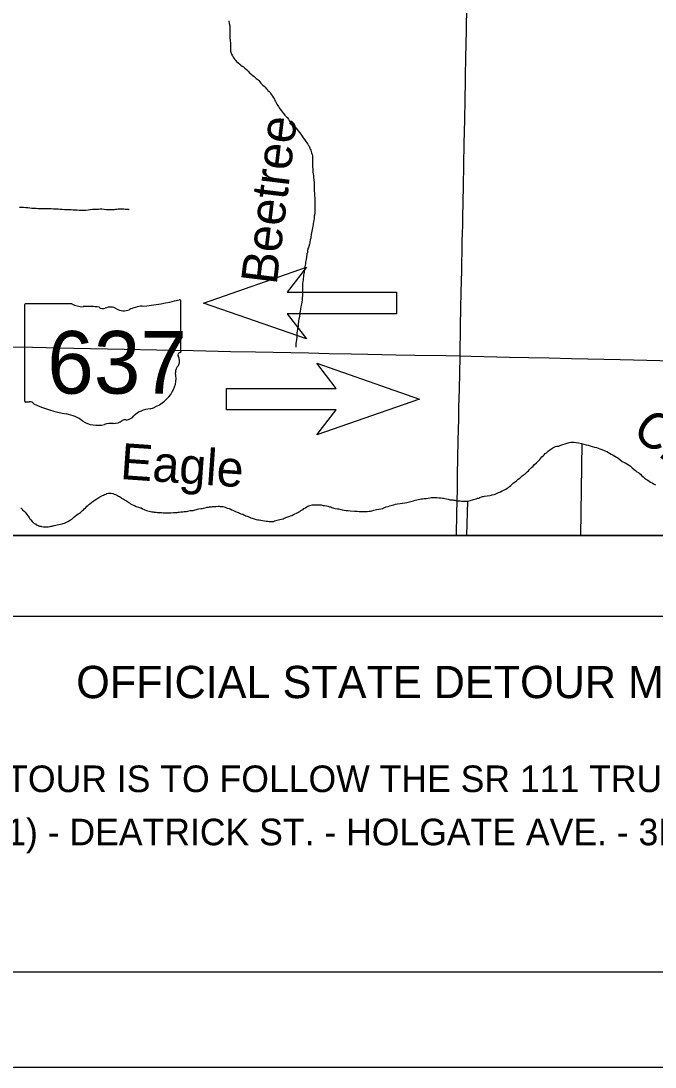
# Model space of a CAD drawing. Extents: x -483 to 680, y 0 to 440.
# Drawn here: x 177 to 243.8, y 0 to 110.1 of the extents above; entities that cross this region are included whole.
import ezdxf

# ---------------------------------------------------------------- set-up
doc = ezdxf.new("R2010")
doc.units = 0
for name, color, linetype in [('Default', 7, 'Continuous'), ('GM_X_Minor_Lake_Text', 7, 'Continuous'), ('GM_X_Minor_River', 7, 'Continuous'), ('GM_X_State_Location', 7, 'Continuous'), ('GM_X_State_Route', 7, 'Continuous'), ('GM_X_State_Shield', 7, 'Continuous'), ('GM_X_Township_Road', 7, 'Continuous'), ('PM_P_Cells', 7, 'Continuous'), ('SH_Border', 7, 'Continuous'), ('SH_Cut_Line', 7, 'Continuous'), ('SH_Text', 7, 'Continuous')]:
    doc.layers.add(name, color=color, linetype=linetype)

msp = doc.modelspace()

# ---------------------------------------------------------------- linework, layer by layer
at = {"layer": 'GM_X_Minor_River'}
for p, q in [((236.06, 65.64), (235.9, 55.95)), ((224.01, 59.59), (223.91, 55.95))]:
    msp.add_line(p, q, dxfattribs=at)
for points in [[(198.88, 110.16), (198.92, 109.88), (198.98, 109.61), (198.99, 109.37), (199.01, 109.14), (199.01, 108.93)], [(199.01, 108.93), (198.99, 108.74), (198.99, 108.57), (198.99, 108.43), (199.01, 108.3), (199.03, 108.19), (199.03, 108.02), (199.05, 107.86), (199.05, 107.64), (199.05, 107.48), (199.05, 107.39), (199.05, 107.28), (199.07, 107.14), (199.08, 106.95), (199.1, 106.84), (199.18, 106.63), (199.27, 106.48), (199.33, 106.34), (199.43, 106.21), (199.52, 106.06), (199.62, 105.96), (199.71, 105.87), (200.03, 105.58), (200.17, 105.49), (200.3, 105.39), (200.43, 105.29), (200.58, 105.16), (200.75, 105.01), (200.93, 104.86), (201.08, 104.68), (201.25, 104.53), (201.4, 104.4), (201.55, 104.28), (201.78, 104.09), (201.93, 103.96), (202.04, 103.85), (202.16, 103.71), (202.27, 103.6), (202.37, 103.48), (202.48, 103.37), (202.6, 103.27), (202.71, 103.16), (202.82, 103.04), (202.92, 102.95), (203.01, 102.82), (203.15, 102.7), (203.24, 102.59), (203.32, 102.47), (203.39, 102.36), (203.49, 102.21), (203.58, 102.05), (203.68, 101.9), (203.75, 101.77), (203.81, 101.65), (203.87, 101.52), (203.94, 101.39), (204.04, 101.24), (204.11, 101.12), (204.19, 100.99), (204.3, 100.84), (204.42, 100.68), (204.53, 100.53), (204.66, 100.38), (204.78, 100.23), (204.91, 100.09), (205.02, 99.96), (205.16, 99.81), (205.29, 99.6), (205.48, 99.41), (205.65, 99.22), (205.8, 99.04), (205.95, 98.87), (206.33, 98.4), (206.46, 98.23), (206.6, 98.02), (206.73, 97.83), (206.86, 97.65), (207, 97.43), (207.11, 97.29), (207.2, 97.16), (207.28, 97.04), (207.34, 96.95), (207.37, 96.85), (207.43, 96.74), (207.47, 96.64), (207.51, 96.53), (207.56, 96.4), (207.6, 96.26), (207.64, 96.15), (207.68, 96.06), (207.7, 95.94), (207.7, 95.85), (207.71, 95.69), (207.71, 95.6), (207.71, 95.43), (207.71, 95.33), (207.71, 95.24), (207.71, 95.12), (207.71, 94.93), (207.71, 94.76), (207.73, 94.53)], [(207.73, 94.53), (207.73, 94.36), (207.75, 94.21), (207.77, 94.04), (207.79, 93.83), (207.81, 93.72), (207.82, 93.6), (207.84, 93.45), (207.84, 93.34), (207.86, 93.18), (207.86, 93.07), (207.86, 92.98), (207.86, 92.84), (207.88, 92.69), (207.88, 92.58), (207.88, 92.48), (207.88, 92.33), (207.88, 92.22), (207.9, 91.99), (207.92, 91.68), (207.93, 91.55), (207.93, 91.42), (207.93, 91.21), (207.93, 91.07), (207.93, 90.98), (207.93, 90.81), (207.93, 90.66), (207.93, 90.52), (207.93, 90.37), (207.93, 90.24), (207.93, 90.12), (207.93, 89.93), (207.91, 89.69), (207.89, 89.59), (207.89, 89.5), (207.87, 89.33), (207.85, 89.12), (207.82, 88.98), (207.78, 88.79), (207.74, 88.51), (207.7, 88.36), (207.66, 88.19), (207.64, 88.02), (207.6, 87.84), (207.57, 87.64), (207.53, 87.39), (207.51, 87.27), (207.47, 87.1), (207.43, 86.89), (207.41, 86.78), (207.37, 86.63), (207.32, 86.38), (207.26, 86.27), (207.22, 86.17), (207.2, 86.08), (207.18, 85.98), (207.16, 85.74), (207.11, 85.64), (207.09, 85.51), (207.07, 85.34), (207.05, 85.24), (207.03, 85.05), (206.99, 84.86), (206.97, 84.77), (206.95, 84.56), (206.91, 84.44), (206.87, 84.12), (206.84, 83.97), (206.82, 83.7), (206.78, 83.51), (206.76, 83.38), (206.74, 83.21), (206.72, 83.04), (206.7, 82.89), (206.68, 82.66), (206.66, 82.53), (206.64, 82.32), (206.64, 82.09), (206.64, 81.82), (206.64, 81.69), (206.64, 81.52), (206.64, 81.2), (206.62, 81.02), (206.6, 80.82), (206.56, 80.49), (206.51, 80.21), (206.47, 80), (206.45, 79.85), (206.43, 79.75), (206.41, 79.6), (206.37, 79.37), (206.33, 79.05), (206.27, 78.74), (206.24, 78.57), (206.22, 78.38), (206.2, 78.27), (206.18, 77.98), (206.12, 77.72), (206.08, 77.41), (206.04, 77.3), (206.04, 76.86)], [(176.86, 90.54), (177.07, 90.52), (177.28, 90.52), (177.51, 90.5), (177.72, 90.48), (177.93, 90.46), (178.14, 90.42), (178.4, 90.42), (178.61, 90.42), (178.8, 90.4), (179.01, 90.4), (179.2, 90.4), (179.39, 90.4), (179.58, 90.4), (180.19, 90.38), (180.42, 90.36), (180.7, 90.34), (180.91, 90.34), (181.12, 90.32), (181.35, 90.32), (181.58, 90.3), (181.83, 90.3), (182.05, 90.28), (182.28, 90.28), (182.51, 90.26), (182.72, 90.26), (182.93, 90.24), (183.12, 90.23), (183.38, 90.23), (183.61, 90.23), (183.84, 90.23), (184.07, 90.25), (184.3, 90.27), (184.54, 90.31), (184.79, 90.31), (185, 90.32), (185.17, 90.32), (185.34, 90.34), (185.51, 90.34), (185.78, 90.32), (185.99, 90.3), (186.16, 90.3), (186.31, 90.28), (186.45, 90.28), (186.58, 90.28), (186.67, 90.28), (186.81, 90.3), (186.96, 90.32), (187.09, 90.32), (187.24, 90.34), (187.38, 90.34), (187.53, 90.34), (187.64, 90.34), (187.74, 90.34), (187.83, 90.34), (187.99, 90.32), (188.16, 90.32), (188.27, 90.31), (188.33, 90.3), (188.35, 90.31), (188.39, 90.28)], [(206.04, 76.86), (205.97, 76.37), (205.96, 76.18), (205.95, 75.91), (205.93, 75.78), (205.93, 75.78)], [(223.25, 59.6), (223.39, 59.59), (223.54, 59.59), (223.67, 59.59), (223.82, 59.59), (223.99, 59.59), (224.17, 59.61), (224.32, 59.65), (224.41, 59.69), (224.53, 59.72), (224.66, 59.76), (224.79, 59.8), (224.93, 59.84), (225.08, 59.89), (225.21, 59.91), (225.31, 59.95), (225.5, 60.03), (225.59, 60.06), (225.69, 60.08), (225.8, 60.12), (226.37, 60.18), (226.52, 60.21), (226.62, 60.23), (226.81, 60.29), (226.94, 60.33), (227.06, 60.38), (227.27, 60.48), (227.48, 60.55), (227.67, 60.65), (227.86, 60.72), (228.05, 60.84), (228.2, 60.93), (228.33, 61.01), (228.45, 61.12), (228.58, 61.23), (228.71, 61.37), (228.87, 61.5), (229.02, 61.63), (229.21, 61.76), (229.36, 61.88), (229.53, 61.99), (229.65, 62.1), (229.78, 62.24), (229.97, 62.39), (230.16, 62.54), (230.31, 62.65), (230.43, 62.77), (230.52, 62.86), (230.62, 62.98), (230.77, 63.13), (230.92, 63.28), (231.09, 63.45), (231.27, 63.6), (231.4, 63.73), (231.53, 63.87), (231.63, 63.98), (231.74, 64.11), (231.86, 64.23), (231.97, 64.36), (232.1, 64.45), (232.2, 64.59), (232.33, 64.68), (232.43, 64.78), (232.52, 64.85), (232.7, 65), (232.79, 65.06), (232.89, 65.14), (233, 65.21), (233.3, 65.32), (233.42, 65.36), (233.53, 65.36), (233.63, 65.38), (233.84, 65.46), (234.07, 65.53), (234.31, 65.63), (234.52, 65.68), (234.71, 65.74), (234.9, 65.78), (235.07, 65.79), (235.26, 65.79), (235.47, 65.77), (235.7, 65.72), (236.02, 65.66), (236.25, 65.58), (236.5, 65.52), (236.73, 65.47), (236.94, 65.41), (237.16, 65.35), (237.39, 65.27), (237.6, 65.22), (237.77, 65.16), (237.96, 65.1), (238.17, 65.03), (238.42, 64.91), (238.57, 64.85), (238.7, 64.8), (239.14, 64.53), (239.35, 64.43), (239.52, 64.32), (239.69, 64.22), (239.86, 64.13)], [(239.86, 64.13), (240.05, 63.97), (240.32, 63.76), (240.62, 63.63), (240.81, 63.52), (240.98, 63.4), (241.13, 63.31), (241.25, 63.19), (241.36, 63.08), (241.55, 62.91), (241.7, 62.81), (241.84, 62.68), (242.01, 62.58), (242.1, 62.52), (242.22, 62.41), (242.39, 62.26), (242.5, 62.14), (242.67, 61.99), (242.86, 61.86), (242.99, 61.78), (243.13, 61.69), (243.3, 61.59), (243.47, 61.51), (243.6, 61.42), (243.81, 61.3)], [(176.99, 58.88), (177.08, 58.8), (177.16, 58.68), (177.33, 58.51), (177.43, 58.42), (177.54, 58.28), (177.63, 58.17), (177.73, 58.02), (177.86, 57.87), (177.94, 57.73), (178.05, 57.6), (178.18, 57.45), (178.28, 57.35), (178.41, 57.24), (178.53, 57.18), (178.62, 57.1), (178.73, 57.05), (178.87, 56.99), (178.96, 56.95), (179.08, 56.93), (179.17, 56.91), (179.36, 56.89), (179.7, 56.87), (179.88, 56.87), (180.07, 56.91), (180.18, 56.93), (180.29, 56.96), (180.39, 56.98), (180.5, 57.02), (180.66, 57.06), (180.81, 57.08), (180.98, 57.11), (181.17, 57.15), (181.34, 57.19), (181.45, 57.21), (181.57, 57.27), (181.74, 57.34), (181.85, 57.4), (181.95, 57.45), (182.12, 57.55), (182.22, 57.61), (182.35, 57.7), (182.54, 57.85), (182.71, 58), (182.9, 58.15), (183.03, 58.25), (183.17, 58.32), (183.26, 58.4), (183.36, 58.5), (183.47, 58.59), (183.57, 58.67), (183.64, 58.78), (183.78, 58.87), (183.87, 58.95), (183.95, 59.04), (184.04, 59.14), (184.14, 59.22), (184.27, 59.31), (184.39, 59.39), (184.48, 59.46), (184.58, 59.54), (184.69, 59.63), (184.81, 59.73), (185, 59.84), (185.32, 60.05), (185.45, 60.1), (185.59, 60.16), (185.68, 60.2), (185.81, 60.27), (185.93, 60.33), (186.06, 60.37), (186.21, 60.41), (186.39, 60.42), (186.5, 60.41), (186.67, 60.37), (186.8, 60.33), (186.97, 60.27), (187.15, 60.18), (187.28, 60.12), (187.39, 60.06), (187.49, 60), (187.58, 59.91), (187.75, 59.81), (187.87, 59.74), (187.98, 59.68), (188.1, 59.6), (188.21, 59.53), (188.32, 59.45), (188.42, 59.39), (188.53, 59.3), (188.68, 59.22)], [(204.98, 57.9), (205.2, 57.98), (205.38, 58.03), (205.51, 58.07), (205.7, 58.18), (205.83, 58.26), (206, 58.32), (206.16, 58.39), (206.25, 58.45), (206.37, 58.5), (206.48, 58.6), (206.61, 58.66), (206.71, 58.71), (206.8, 58.79), (206.96, 58.86), (207.11, 58.98), (207.22, 59.05), (207.32, 59.09), (207.43, 59.13), (207.66, 59.18), (207.76, 59.18), (207.93, 59.2), (208.12, 59.2), (208.23, 59.2), (208.42, 59.2), (208.61, 59.18), (208.82, 59.14), (208.95, 59.12), (209.18, 59.07), (209.33, 59.05), (209.48, 58.99), (209.64, 58.99), (209.73, 58.91), (210.06, 58.82), (210.32, 58.76), (210.42, 58.76), (210.82, 58.66), (211.23, 58.6), (211.44, 58.6), (211.65, 58.56), (212.11, 58.53), (212.41, 58.51), (212.62, 58.5), (212.77, 58.49), (212.94, 58.48), (213.17, 58.5), (213.44, 58.5), (213.67, 58.52), (213.82, 58.54), (213.95, 58.56), (214.05, 58.58), (214.16, 58.63), (214.45, 58.69), (214.69, 58.75), (214.9, 58.78), (215.06, 58.82), (215.15, 58.84), (215.27, 58.9), (215.44, 58.97), (215.65, 59.03), (215.85, 59.1), (216.08, 59.16), (216.25, 59.2), (216.43, 59.25), (216.65, 59.31), (216.94, 59.35), (217.19, 59.37), (217.41, 59.4), (217.62, 59.44), (217.78, 59.46), (217.91, 59.5), (218.35, 59.63), (218.5, 59.68), (218.67, 59.72), (218.84, 59.76), (219.01, 59.8), (219.15, 59.82), (219.28, 59.83), (219.45, 59.85), (219.66, 59.87), (219.87, 59.91), (220.04, 59.93), (220.19, 59.95), (220.34, 59.96), (220.57, 59.96), (220.78, 59.96), (221.01, 59.94), (221.22, 59.92), (221.39, 59.9), (221.5, 59.89), (221.64, 59.85), (221.81, 59.83), (221.98, 59.79), (222.19, 59.73), (222.38, 59.71), (222.47, 59.71), (222.59, 59.69), (222.68, 59.67), (222.87, 59.63), (223.08, 59.61), (223.25, 59.6)], [(188.68, 59.22), (188.84, 59.16), (188.95, 59.11), (189.14, 59.03), (189.39, 58.93), (189.56, 58.88), (189.65, 58.86), (189.79, 58.78), (189.98, 58.7), (190.22, 58.61), (190.77, 58.47), (190.91, 58.45), (191.02, 58.43), (191.25, 58.42), (191.38, 58.4), (191.53, 58.4), (191.67, 58.38), (191.8, 58.38), (191.97, 58.36), (192.16, 58.36), (192.29, 58.35), (192.41, 58.34), (192.56, 58.35), (192.77, 58.35), (193.06, 58.37), (193.26, 58.37), (193.44, 58.39), (193.55, 58.41), (193.66, 58.43), (193.84, 58.45), (194.03, 58.46), (194.18, 58.48), (194.29, 58.48), (194.42, 58.5), (194.58, 58.54), (194.81, 58.58), (194.98, 58.59), (195.13, 58.61), (195.24, 58.63), (195.34, 58.65), (195.47, 58.69), (195.6, 58.73), (195.74, 58.76), (195.95, 58.8), (196.1, 58.82), (196.21, 58.84), (196.36, 58.88), (196.5, 58.91), (196.61, 58.93), (196.76, 58.95), (196.86, 58.97), (196.95, 58.97), (197.05, 58.99), (197.18, 59.01), (197.37, 59.02), (197.51, 59.02), (197.75, 59.04), (197.87, 59.04), (197.98, 59.02), (198.11, 59.02), (198.25, 59.02), (198.49, 58.93), (198.72, 58.85), (198.91, 58.79), (199.03, 58.77), (199.2, 58.68), (199.37, 58.6), (199.58, 58.5), (199.77, 58.43), (199.9, 58.39), (200, 58.33), (200.17, 58.26), (200.36, 58.2), (200.47, 58.14), (200.57, 58.1), (200.68, 58.05), (200.81, 57.99), (200.93, 57.95), (201.06, 57.89), (201.19, 57.83), (201.33, 57.78), (201.46, 57.76), (201.57, 57.72), (201.76, 57.66), (201.93, 57.62), (202.07, 57.6), (202.26, 57.57), (202.45, 57.53), (202.66, 57.51), (202.83, 57.49), (202.98, 57.47), (203.13, 57.45), (203.3, 57.43), (203.45, 57.45), (203.59, 57.45), (203.7, 57.5), (203.97, 57.58), (204.27, 57.65), (204.6, 57.73), (204.71, 57.79), (204.98, 57.9)]]:
    msp.add_lwpolyline(points, dxfattribs=at)
at = {"layer": 'GM_X_State_Route'}
msp.add_lwpolyline([(175.75, 75.83), (178.23, 75.78), (182.58, 75.7), (187.87, 75.59), (191.29, 75.51), (195.17, 75.43), (199.06, 75.34), (201.7, 75.31), (207.29, 75.19), (209.47, 75.14), (211.8, 75.1), (213.51, 75.06), (216.46, 75), (218.48, 74.96), (221.75, 74.9), (223.24, 74.87), (224.39, 74.84), (228.43, 74.75), (230.45, 74.7), (232.63, 74.66), (234.96, 74.6), (240.08, 74.49), (247.08, 74.31)], dxfattribs=at)
at = {"layer": 'GM_X_State_Shield'}
for p, q in [((193.85, 75.39), (193.85, 80.62)), ((177.37, 80.2), (177.37, 70.19)), ((182.36, 80.37), (177.54, 80.37)), ((193.85, 75.39), (193.85, 75.39))]:
    msp.add_line(p, q, dxfattribs=at)
for centre, major_axis, start_param, end_param in [((187.98, 94.01), (17.48, 0), 4.814394, 5.042369), ((193.67, 80.64), (0.183, 0), 6.141152, 7.989035), ((177.56, 80.22), (0.191, 0), 1.712693, 3.28349), ((183.51, 81.53), (1.85, 0), 4.042523, 4.731795), ((184.12, 74.76), (6.65, 0), 1.404758, 1.657858), ((185.63, 80.27), (0.534, 0), 3.836095, 5.185415), ((186.42, 79.12), (1.11, 0), 0.950623, 2.079405), ((187.85, 80.7), (1.34, 0), 4.081561, 5.145723), ((190.21, 77.32), (3.52, 0), 1.699011, 2.107814), ((193.81, 75), (0.284, 0), 1.883978, 3.671073), ((193.66, 75.37), (0.196, 0), 5.05454, 6.418171), ((194.51, 73.2), (1.24, 0), 2.387724, 3.262537), ((192, 74.34), (1.7, 0), 5.934695, 6.695948), ((188.96, 72.53), (4.37, 0), 5.101752, 6.440018), ((177.56, 70.17), (0.193, 0), 3.00124, 4.508301), ((177.59, 71.2), (1.47, 0), 4.665946, 4.897461), ((177.89, 69.62), (0.53, 0), 0.519207, 1.627899), ((184.58, 78.61), (12.62, 0), 4.195997, 4.488961), ((180.82, 65.7), (3.95, 0), 0.823519, 1.323587), ((187.77, 69.22), (1.41, 0), 4.937069, 5.64225), ((190.8, 67.39), (2.39, 0), 1.647645, 2.488434), ((185.09, 69.57), (2.51, 0), 4.026481, 4.996735), ((186.54, 66.11), (2.06, 0), 1.495662, 1.94098), ((186.72, 68.82), (1.33, 0), 4.691044, 5.507374), ((187.93, 67.85), (0.376, 0), 1.147584, 2.315152)]:
    msp.add_ellipse(centre, major_axis=major_axis, ratio=0.8, start_param=start_param, end_param=end_param, dxfattribs=at)
at = {"layer": 'GM_X_Township_Road'}
for points in [[(223.89, 107.94), (223.91, 108.89), (223.95, 112), (224.01, 114.48), (224.07, 118.68), (224.17, 122.87), (224.2, 124.58), (224.22, 125.28)], [(223.24, 74.87), (223.29, 78.04), (223.32, 79.91), (223.35, 81.57), (223.41, 83.87), (223.46, 86.67), (223.47, 87.14), (223.48, 87.6), (223.51, 88.84), (223.52, 89.46), (223.6, 92.73), (223.67, 97.23), (223.73, 99.72), (223.75, 100.5), (223.77, 101.12), (223.82, 104.54), (223.85, 106.09), (223.89, 107.94)], [(222.85, 55.95), (222.91, 58.3), (222.96, 60.79), (222.98, 62.34), (223.04, 65.92), (223.09, 68.25), (223.12, 69.49), (223.16, 71.36), (223.24, 74.78), (223.24, 74.87)]]:
    msp.add_lwpolyline(points, dxfattribs=at)
at = {"layer": 'PM_P_Cells'}
for p, q in [((196.22, 80.44), (207.06, 84.2)), ((207.06, 84.2), (205.03, 81.57)), ((205.03, 81.57), (216.55, 81.57)), ((216.55, 81.57), (216.55, 79.31)), ((207.06, 76.67), (196.22, 80.44)), ((216.55, 79.31), (205.03, 79.31)), ((205.03, 79.31), (207.06, 76.67)), ((208.15, 74.09), (218.98, 70.32)), ((210.18, 71.45), (208.15, 74.09)), ((198.66, 69.19), (198.66, 71.45)), ((198.66, 71.45), (210.18, 71.45)), ((218.98, 70.32), (208.15, 66.56)), ((210.18, 69.19), (198.66, 69.19)), ((208.15, 66.56), (210.18, 69.19))]:
    msp.add_line(p, q, dxfattribs=at)
at = {"layer": 'SH_Border'}
msp.add_lwpolyline([(30, 430), (670, 430), (670, 10), (30, 10)], close=True, dxfattribs=at)
at = {"layer": 'SH_Cut_Line'}
msp.add_lwpolyline([(0, 0), (680, 0), (680, 440), (0, 440)], close=True, dxfattribs=at)
msp.add_lwpolyline([(45.61, 281.49), (45.61, 55.95), (373.8, 55.95)], dxfattribs=at)
at = {"layer": 'SH_Text'}
for points in [[(37.11, 404.45), (394.11, 404.45), (394.11, 47.45), (37.11, 47.45)], [(45.61, 395.95), (385.61, 395.95), (385.61, 55.95), (45.61, 55.95)]]:
    msp.add_lwpolyline(points, close=True, dxfattribs=at)

# ---------------------------------------------------------------- texts
at = {"layer": 'Default'}
msp.add_text('OFFICIAL STATE DETOUR MAP', height=3.4, dxfattribs=at).set_placement((182.82, 38.84))
at = {"layer": 'GM_X_Minor_Lake_Text'}
for s, height, rotation, p in [('Beetree', 3.79, 83.0338, (203.92, 82.28)), ('Creek', 3.789, 321.0413, (241.19, 66.7)), ('Eagle', 3.79, 356.0436, (187.39, 61.92))]:
    msp.add_text(s, height=height, rotation=rotation, dxfattribs=at).set_placement(p)
at = {"layer": 'GM_X_State_Location'}
msp.add_text('637', height=0.00947, rotation=0, dxfattribs=at).set_placement((182.08, 73.84))
for s in ['s', 'r']:
    msp.add_text(s, height=0.00947, dxfattribs=at).set_placement((185.43, 74.53))
at = {"layer": 'GM_X_State_Shield'}
msp.add_text('637', height=6.592, dxfattribs=at).set_placement((179.77, 70.9))
at = {"layer": 'SH_Text'}
for s, p in [('NOTE: THE OFFICIAL STATE DETOUR IS TO FOLLOW THE SR 111 TRUCK ROUTE WITHIN THE CITY OF DEFIANCE.', (118.24, 28.95)), ('CLINTON ST. (SR 111) - DEATRICK ST. - HOLGATE AVE. - 3RD ST. - CLINTON ST. (SR 111)', (139.46, 23.35))]:
    msp.add_text(s, height=2.8, dxfattribs=at).set_placement(p)

doc.saveas('drawing.dxf')
